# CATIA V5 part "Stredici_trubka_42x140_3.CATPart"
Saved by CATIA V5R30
Part number: Stredici_trubka_42x140_3
Definition: E 1160_42x140
Nomenclature: E 1160_42x140
Source: Unknown
Description: PART--DESC
Bounding box of the stored display mesh (mm): x 166 to 208, y -157.99 to -116.01, z -258 to -118
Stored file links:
  E:\Bakalarka\Model\Forma_v7\Stredici_trubka_42x140_3.CATPart
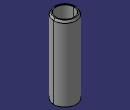
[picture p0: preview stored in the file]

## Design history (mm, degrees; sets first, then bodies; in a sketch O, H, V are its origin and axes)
Body1 "MANIFOLD_SOLID_BREP #3906" (main body)
  Solid1: solid without history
